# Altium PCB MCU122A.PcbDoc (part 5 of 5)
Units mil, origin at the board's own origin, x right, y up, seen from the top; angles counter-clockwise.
Board outline 4950 x 3450 mil, 4 copper layers (Top Layer, Signal Layer 1, Signal Layer 2, Bottom Layer), stack 60 mil thick; 257 components, 158 nets, 848 pads, 1971 vias.
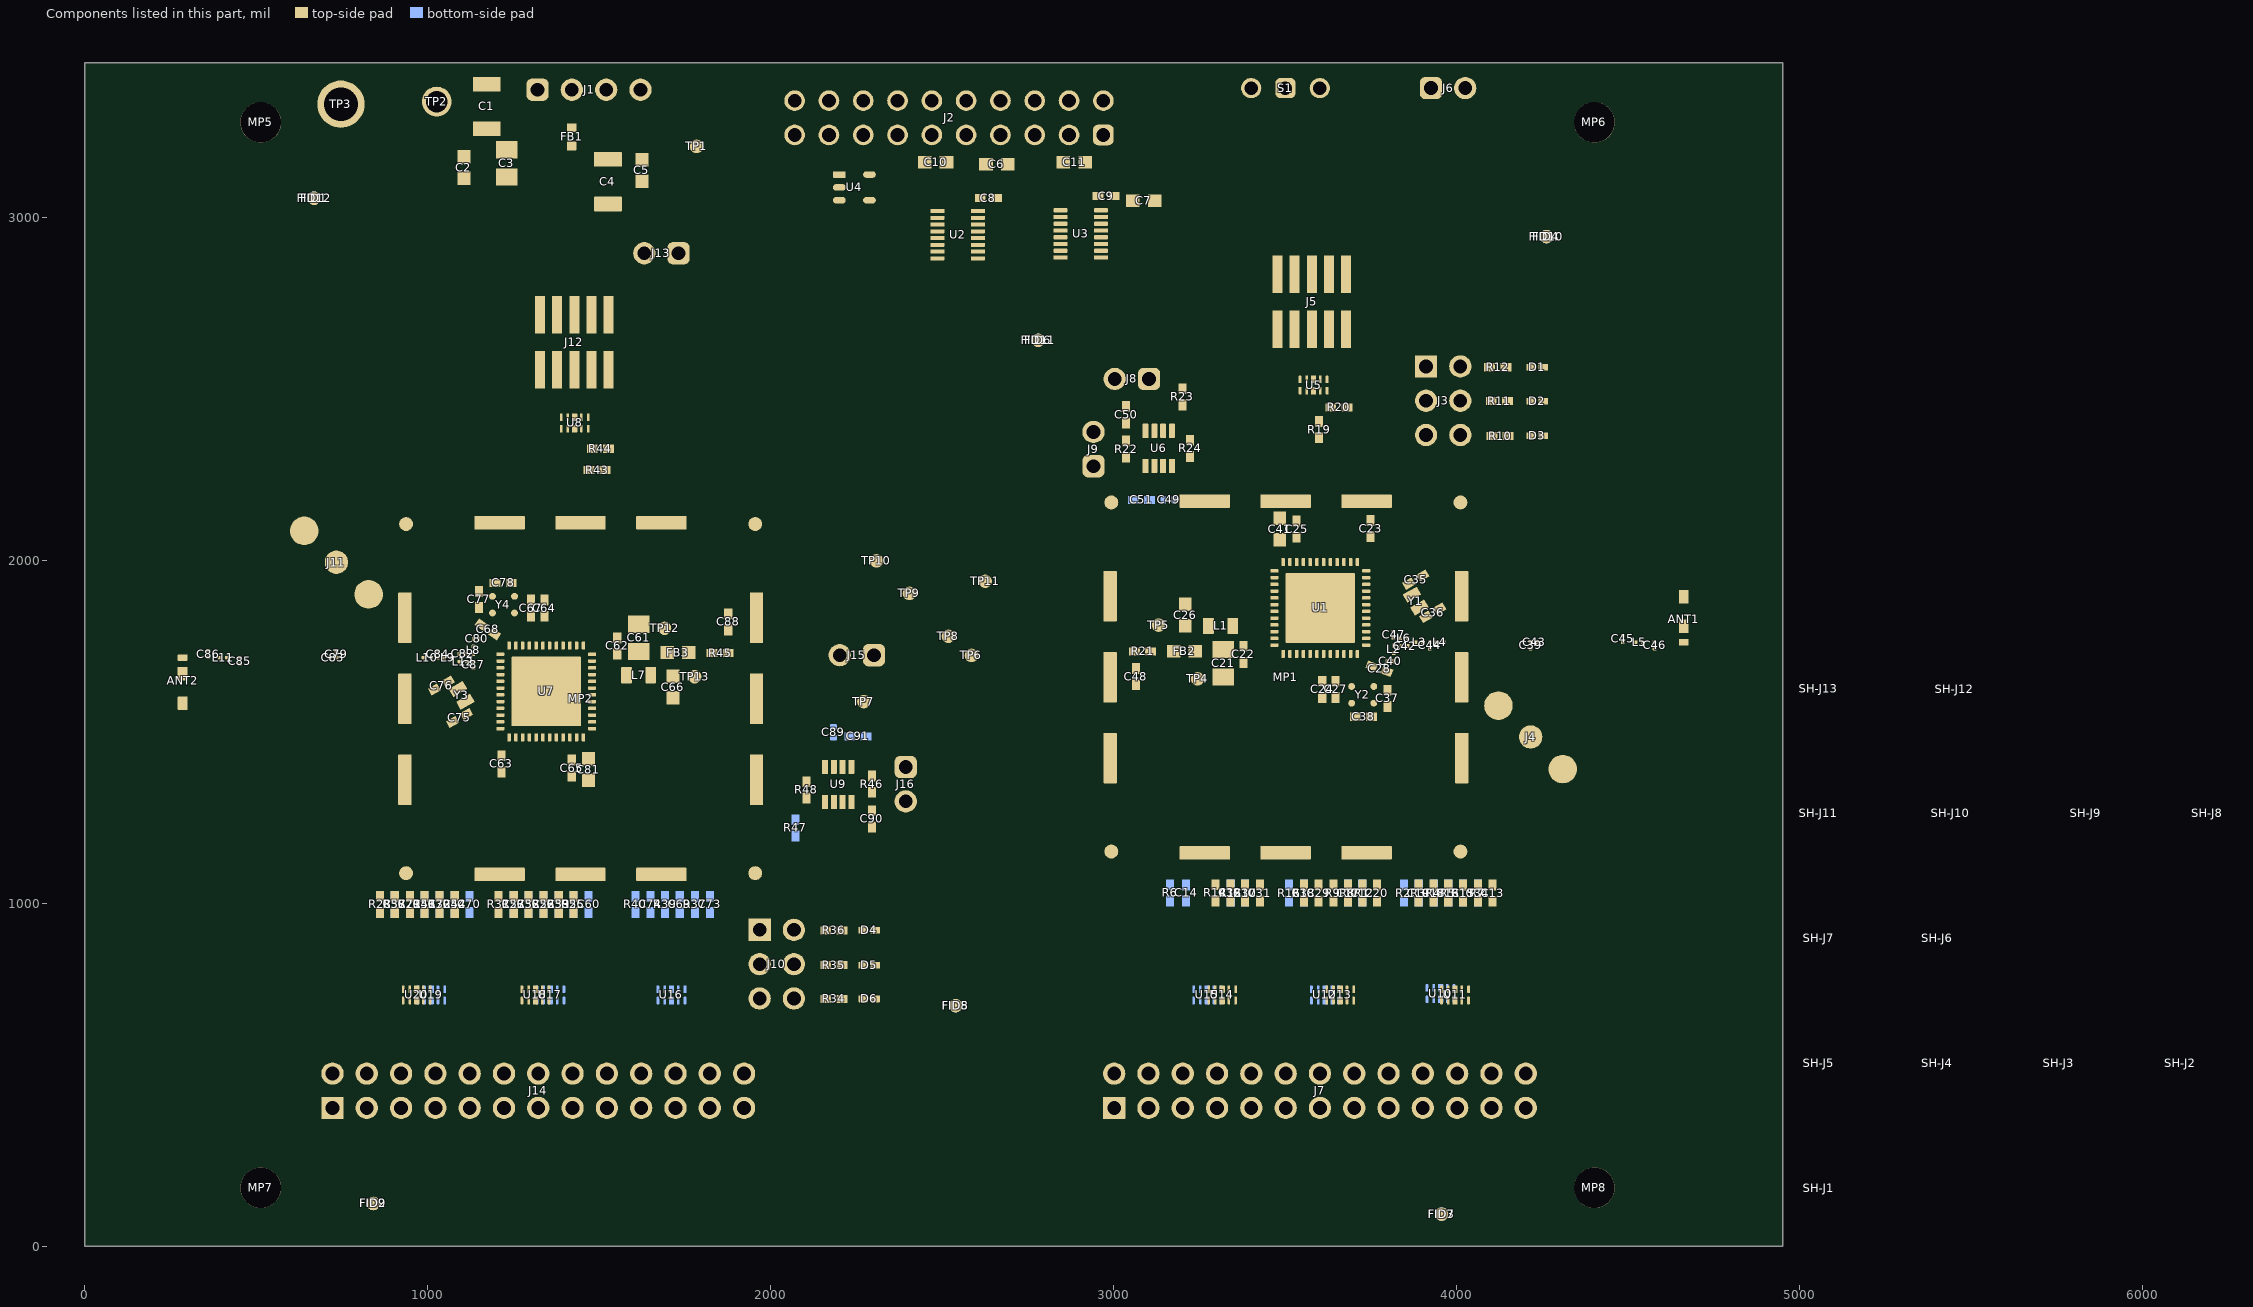
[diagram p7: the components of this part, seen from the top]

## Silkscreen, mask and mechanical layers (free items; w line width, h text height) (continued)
M9 Title Sheet:
  drawing of 57 lines, arcs and shapes, not listed
  text "1" at 739.84,8036.5 h70
  text "2" at 3235.5,8036.5 h70
  text "3" at 5724.84,8036.5 h70
  text "4" at 8231.51,8036.5 h70
  text "5" at 10730.5,8036.5 h70
  text "6" at 13235.5,8036.5 h70
  text "A" at -416.5,6893.5 h70
  text "A" at 14383.5,6893.5 h70
  text "B" at -416.5,4513.5 h70
  text "B" at 14383.5,4513.5 h70
  text "C" at -416.5,2138.5 h70
  text "C" at 14383.5,2138.5 h70
  text "PROJECT TITLE:" at 11343.5,277.5 h45
  text ".PRJ_Title" at 11393.5,144.17 h70
  text "DESIGNED FOR:" at 11343.5,-23.5 h45
  text ".PRJ_Customer" at 11393.5,-163.5 h70
  text "D" at -416.5,-231.5 h70
  text "D" at 14383.5,-231.5 h70
  text "FILE NAME:" at 11343.5,-323.5 h45
  text ".PCB_File_Name_No_Path" at 11393.5,-443.5 h70
  text "Texas Instruments (TI) and/or its licensors do not warrant the accuracy or completeness of this specification" at 6374,-605.34 h45
  text "ENGINEER:" at 11343.5,-613.5 h45
  text "LAYOUT BY:" at 12848.5,-613.5 h45
  text "or any information contained therein. TI and/or its licensors do not warrant that this design will meet" at 6329.01,-718 h45
  text ".PRJ_Engineer" at 11393.5,-768.49 h70
  text ".PCB_Layout" at 12899,-768.49 h70
  text "the specifications, will be suitable for your application or fit for any particular purpose, or will operate in" at 6329.01,-830.67 h45
  text ".Layer_Name" at 577,-858.49 h60
  text "ALTIUM DESIGNER VERSION:" at 12848.5,-923.5 h45
  text "an implementation. TI and/or its licensors do not warrant that the design is production worthy. You should" at 6329.01,-943.33 h45
  text "completely validate and test your design implementation to confirm the system functionality for your application." at 6374,-1056 h45
  text ".print_Scale" at 11393.5,-1056.83 h70
  text ".Application_BuildNumber" at 12899,-1056.83 h70
  text "1" at 739.84,-1263.5 h70
  text "2" at 3235.5,-1263.5 h70
  text "3" at 5724.84,-1263.5 h70
  text "4" at 8231.51,-1263.5 h70
  text "5" at 10730.5,-1263.5 h70
  text "6" at 13235.5,-1263.5 h70
M10 Fab Notes:
  drawing of 189 lines, arcs and shapes, not listed
  text "DESIGN INFORMATION" at 12382.02,6356.17 h60
  text "MIN. TRACK WIDTH:" at 11737.46,6224.05 h60
  text "6.5" at 12785.43,6224.05 h60
  text "MIL" at 12988.46,6224.05 h60
  text "Notes" at 7057.24,6141.89 h60
  text "5" at 12834.65,6112.2 h60
  text "MIN. CLEARANCE:" at 11737.46,6099.92 h60
  text "MIL" at 12988.46,6099.92 h60
  text "RF Nets must maintain 50ohm characteristic impedance +/-10%" at 7047.4,6033.93 h60
  text "MIN. VIA PAD SIZE:" at 11737.46,5975.8 h60
  text "11.457" at 12610.85,5975.8 h60
  text "MIL" at 12988.46,5975.8 h60
  text "RF nets are GCPW lines with 6.5mil width and ~6.25mil gap to GND" at 7047.4,5935.51 h60
  text "0.05mm (2MIL)" at 12432.46,5845.9 h60
  text "MINIMUM ANNULAR RING" at 11408.23,5837.67 h60
  text "EXTERNAL" at 13140.46,5837.67 h60
  text "PER" at 11608.23,5727.55 h60
  text "IPC-D-275 CLASS 2 LEVEL C" at 11828.23,5727.54 h60
  text "MIL, HOLES" at 13316.46,5627.07 h60
  text "+/-" at 12924,5618.48 h60
  text "+/-" at 13778,5618.48 h60
  text "REGISTRATION TOLERANCES:" at 11408.23,5617.42 h60
  text "METAL" at 12608,5617.42 h60
  text "5" at 13184.2,5617.42 h60
  text "3" at 14017.2,5617.42 h60
  text "MIL" at 14133.46,5617.42 h60
  text "HOLE SIZE TOLERANCE (UNLESS OTHERWISE SPECIFIED):" at 11408.23,5519.1 h60
  text "+/-" at 13778,5516.23 h60
  text "3" at 14017.2,5515.17 h60
  text "MIL" at 14133.46,5515.17 h60
  text "MATERIAL:" at 11333.46,5377.52 h60
  text "FR-4 High Tg" at 12319.9,5249 h60
  text "X" at 12175.46,5241.01 h60
  text "FR-4" at 11754.46,5236.49 h60
  text "OTHER" at 13242.46,5236.49 h60
  text "X" at 11958.66,5093.46 h60
  text "62 MIL (1.6mm) +/-10%" at 12074.56,5093.46 h60
  text "THICKNESS:" at 11408.23,5085.24 h60
  text "OTHER" at 13359.46,5085.24 h60
  text "TOLERANCE:" at 11408.23,4946.92 h60
  text "X" at 12256.46,4946.92 h60
  text "ANSI IPC-6012 TYPE 3 CLASS 2" at 12434.48,4946.92 h60
  text "OTHER +/-" at 12434.46,4802.73 h60
  text "BOW & TWIST:" at 11408.23,4657.54 h60
  text "X" at 12256.46,4657.54 h60
  text "ANSI IPC-6012 TYPE 3 CLASS 2" at 12434.48,4657.54 h60
  text "OTHER +/-" at 12434.46,4510.85 h60
  text "DRILLING:" at 11333.46,4380.23 h60
  text "NC_DRILL FILES" at 13094.46,4275.04 h60
  text "REFERENCE:" at 11408.23,4271.1 h60
  text "X" at 12065.46,4271.01 h60
  text "AS SHOWN" at 12243.46,4271.1 h60
  text "X" at 12966.46,4271.1 h60
  text "X" at 13287.4,4128.85 h60
  text "OTHER" at 13392.46,4128.85 h60
  text "PTH COPPER THICKNESS:" at 11407.91,4125.32 h60
  text "20-30 um" at 12675.14,4125.32 h60
  text "36 um" at 13769.84,4124.17 h60
  text "BOARD FINISH:" at 11333.46,3977.73 h60
  text "SILKSCREEN:" at 11488.68,3867.6 h60
  text "X" at 12446.46,3867.6 h60
  text "TOP" at 12563.46,3867.6 h60
  text "X" at 12956.46,3867.6 h60
  text "BOTTOM" at 13074.46,3867.6 h60
  text "SILKSCREEN COLOR:" at 11488.68,3712.41 h60
  text "X" at 12445.46,3712.41 h60
  text "WHITE" at 12563.46,3712.41 h60
  text "OTHER" at 13074.46,3712.41 h60
  text "X" at 13169.29,3582.68 h60
  text "GREEN" at 12694.46,3568.96 h60
  text "OTHER" at 13312.46,3568.96 h60
  text "SOLDER RESIST COLOR:" at 11488.68,3562.1 h60
  text "RED" at 13669,3550.03 h60
  text "X" at 12576.46,3414.71 h60
  text "MATTE" at 12694.46,3414.71 h60
  text "SEMI-GLOSS" at 13312,3414.07 h60
  text "IMMERSION GOLD (ENIG)" at 12394.46,3241.94 h60
  text "ENEPIG" at 13732,3234.72 h60
  text "SURFACE FINISH:" at 11333.46,3233.72 h60
  text "X" at 12216.46,3233.72 h60
  text "IMM. TIN/SILVER OR EQUIV" at 11663,3096.4 h60
  text "OTHER" at 13094.46,3092.47 h60
  text "ARRAY/PANEL:" at 11333.46,2937.09 h60
  text "CUT AND TRIM PER M1 BOARD OUTLINE" at 12394.46,2928.87 h60
  text "N.C. ROUTE" at 12394.46,2792.9 h60
  text "X" at 13082.46,2792.9 h60
  text "V. SCORE" at 13260.46,2792.9 h60
  text "CERTIFICATION:" at 11333.46,2663.77 h60
  text "MATERIALS AND WORKMANSHIP FOR ALL PCBS" at 12058.46,2663.77 h60
  text "TO MEET OR EXCEED THE REQUIREMENTS OF:" at 12058.46,2569.71 h60
  text "X" at 11695.97,2441.08 h60
  text "ANSI IPC-A-600F CLASS ->" at 11823.96,2441.08 h60
  text "X" at 13471.97,2441.08 h60
  text "2" at 13581.96,2441.08 h60
  text "1" at 13266.96,2439.58 h60
  text "3" at 13935.96,2439.58 h60
  text "X" at 12507.97,2293.39 h60
  text "RoHS" at 12635.96,2293.39 h60
  text "OTHER" at 13280.36,2293.39 h60
  text "PER ORDER" at 13677.42,2293.39 h60
  text "ALL BOARDS MUST MEET OR EXCEED UL94-V0 REQUIREMENTS." at 11361,2139.57 h60
  text "PCB MUST BEAR THE UL94V-0 UL REGISTERED MATERIAL ID NUMBER" at 11361,2023.5 h60
  text "ADDITIONAL REQUIREMENTS:" at 11333.46,1854.08 h60
  text "MICROSECTION:" at 11408.23,1746.95 h60
  text "YES" at 12313.96,1746.95 h60
  text "REQUIRED" at 13175.46,1602.62 h60
  text "BARE BOARD ELEC. TEST:" at 11408.23,1599.76 h60
  text "NONE" at 12713.96,1599.76 h60
  text "X" at 13057.46,1599.76 h60
  text "PER ORDER" at 13767.46,1599.76 h60
  text "XX MIL VIAS REQUIRE NON-CONDUCTIVE FILL AND PLANARIZE" at 11576.38,1394.82 h59
  text "XX MIL VIAS REQUIRE CONDUCTIVE FILL AND PLANARIZE" at 11584.38,1290.84 h60
  text "OUTER XX MIL TRACES REQUIRE 50 OHM SINGLE-ENDED IMPEDANCE" at 11583.39,1127.46 h58
  text "LAYER 2 & 3 (INNER LAYERS) XX MIL WIDE, XX MIL SPACE / TRACES REQUIRE 100 OHM DIFFERENTIAL IMPEDANCE" at 11575.39,891.74 h60
  text ".Layer_Name" at 577,-858.49 h60
M11 Gerber Information:
  lines w10: -292,-930.17 6308,-930.17 ; -292,-726.83 6310,-726.83 ; -292,-523.5 -292,-1133.5 3713,-1133.5 6310,-1133.5 6310,-523.5 -291.5,-523.5 -291.5,-1133.5 1284,-1133.5 ; 2173,-1133.5 2173,-523.5 ; 3440,-726.83 3440,-523.5 ; 4280,-726.83 4280,-523.5 ; 4902,-1140 4902,-937.17
  text "ALL ARTWORK VIEWED FROM TOP SIDE" at -228.5,-655.67 h60
  text "BOARD #:" at 2248,-655.67 h60
  text ".PRJ_Number" at 2793.5,-655.67 h60
  text "REV:" at 3638,-655.67 h60
  text ".PCB_Rev" at 3929.5,-655.67 h60
  text "SVN REV:" at 4476,-655.67 h60
  text ".VersionControl_RevNumber" at 4982,-655.67 h60
  text "LAYER NAME =" at -228.5,-858.49 h60
  text "TID #:" at 2248,-859 h60
  text ".TID" at 2793.5,-859 h60
  text "PLOT NAME =" at -228.5,-1064.34 h60
  text ".plot_File_Name" at 577,-1064.34 h60
  text "GENERATED    :" at 2250,-1064.34 h60
  text ".Print_Date" at 3119.5,-1064.34 h60
  text ".Print_Time" at 3848.5,-1064.34 h60
  text "TEXAS INSTRUMENTS" at 5113,-1064.34 h60
M12 Stackup:
  drawing of 295 lines, arcs and shapes, not listed
  text "Layer" at 6750.34,7816.15 h60
  text "Name" at 7160.25,7816.15 h60
  text "Material" at 8099.99,7816.15 h60
  text "Thickness" at 8959.76,7816.15 h60
  text "Constant" at 9609.6,7816.15 h60
  text "Board Layer Stack" at 10179.46,7816.15 h60
  text "Top Overlay" at 7160.25,7696.15 h60
  text "Top Solder" at 7160.25,7576.15 h60
  text "Solder Resist" at 8099.99,7576.15 h60
  text "1.00mil" at 8959.76,7576.15 h60
  text "3.4" at 9609.6,7576.15 h60
  text "1" at 6750.34,7456.15 h60
  text "Top Layer" at 7160.25,7456.15 h60
  text "1.60mil" at 8959.76,7456.15 h60
  text "Dielectric 1" at 7160.25,7336.15 h60
  text "FR-4 High Tg" at 8099.99,7336.15 h60
  text "5.00mil" at 8959.76,7336.15 h60
  text "4.6" at 9609.6,7336.15 h60
  text "2" at 6750.34,7216.15 h60
  text "Signal Layer 1" at 7160.25,7216.15 h60
  text "1.40mil" at 8959.76,7216.15 h60
  text "Dielectric 2" at 7160.25,7096.15 h60
  text "FR-4 High Tg" at 8099.99,7096.15 h60
  text "44.00mil" at 8959.76,7096.15 h60
  text "4.6" at 9609.6,7096.15 h60
  text "3" at 6750.34,6976.15 h60
  text "Signal Layer 2" at 7160.25,6976.15 h60
  text "1.40mil" at 8959.76,6976.15 h60
  text "Dielectric 3" at 7160.25,6856.15 h60
  text "FR-4 High Tg" at 8099.99,6856.15 h60
  text "5.00mil" at 8959.76,6856.15 h60
  text "4.6" at 9609.6,6856.15 h60
  text "4" at 6750.34,6736.15 h60
  text "Bottom Layer" at 7160.25,6736.15 h60
  text "1.60mil" at 8959.76,6736.15 h60
  text "Bottom Solder" at 7160.25,6616.15 h60
  text "Solder Resist" at 8099.99,6616.15 h60
  text "1.00mil" at 8959.76,6616.15 h60
  text "3.4" at 9609.6,6616.15 h60
  text "Bottom Overlay" at 7160.25,6496.15 h60
  text "Total board thickness:" at 6750.34,6376.15 h60
  text "62.00mil" at 8959.76,6376.15 h60
  text ".Layer_Name" at 577,-858.49 h60
M13 Component Bodies Top:
  text ".Layer_Name" at 577,-858.49 h60
M14 Component Bodies Bottom:
  text ".Layer_Name" at 577,-858.49 h60
M15 Courtyards Top:
  text ".Layer_Name" at 577,-858.49 h60
M16 Courtyards Bottom:
  text ".Layer_Name" at 577,-858.49 h60
Drill Drawing:
  circle w10: c5363.72,3165.96 r27.63
  circle w10: c5363.72,2917.32 r27.63
  lines w10: 5336.09,2447.67 5391.34,2447.67 5363.72,2392.42 5336.09,2447.67 ; 5336.09,2516.74 5391.34,2516.74 5391.34,2571.99 5336.09,2571.99 5336.09,2516.74 ; 5336.09,2654.87 5349.9,2654.87 5349.9,2641.06 5377.53,2641.06 5377.53,2654.87 5391.34,2654.87 5391.34,2682.5 5377.53,2682.5 5377.53,2696.31 5349.9,2696.31 5349.9,2682.5 5336.09,2682.5 5336.09,2654.87 ; 5336.09,2765.38 5363.72,2779.19 5391.34,2765.38 5377.53,2793 5391.34,2820.63 5363.72,2806.82 5336.09,2820.63 5349.9,2793 5336.09,2765.38 ; 5336.09,3069.27 5391.34,3069.27 5363.72,3014.02 5336.09,3069.27 ; 5336.09,3290.28 5363.72,3262.66 5391.34,3290.28 5363.72,3317.91 5336.09,3290.28 ; 5347.14,3058.22 5380.29,3058.22 5363.72,3025.07 5347.14,3058.22
  lines w12: 5286,2355.12 8517.65,2355.12 ; 5286,3349.68 8517.65,3349.68 ; 5623.86,2230.8 5623.86,3474 ; 5956.03,2230.8 5956.03,3474 ; 6592.59,2230.8 6592.59,3474 ; 6851.73,2230.8 6851.73,3474 ; 7226.89,2230.8 7226.89,3474 ; 7951.22,2230.8 7951.22,3474 ; 5286,2230.8 8517.65,2230.8 8517.65,3474 5286,3474 5286,2230.8
  text "Symbol" at 5360.59,3386.98 h72
  text "Quantity" at 5661.16,3386.98 h72
  text "Finished Hole Size" at 5993.33,3386.98 h72
  text "Plated" at 6629.89,3386.98 h72
  text "Hole Type" at 6889.03,3386.98 h72
  text "Drill Layer Pair" at 7264.19,3386.98 h72
  text "Hole Tolerance" at 7988.52,3386.98 h72
  text "4" at 5661.16,3262.66 h60
  text "118.11mil (3.000mm)" at 5993.33,3262.66 h60
  text "NPTH" at 6629.89,3262.66 h60
  text "Round" at 6889.03,3262.66 h60
  text "Top Layer - Bottom Layer" at 7264.19,3262.66 h60
  text "1970" at 5661.16,3138.34 h60
  text "8.00mil (0.203mm)" at 5993.33,3138.34 h60
  text "PTH" at 6629.89,3138.34 h60
  text "Round" at 6889.03,3138.34 h60
  text "Top Layer - Bottom Layer" at 7264.19,3138.34 h60
  text "1" at 5661.16,3014.02 h60
  text "8.00mil (0.203mm)" at 5993.33,3014.02 h60
  text "PTH" at 6629.89,3014.02 h60
  text "Round" at 6889.03,3014.02 h60
  text "Top Layer - Bottom Layer" at 7264.19,3014.02 h60
  text "3" at 5661.16,2889.7 h60
  text "39.37mil (1.000mm)" at 5993.33,2889.7 h60
  text "PTH" at 6629.89,2889.7 h60
  text "Round" at 6889.03,2889.7 h60
  text "Top Layer - Bottom Layer" at 7264.19,2889.7 h60
  text "+/-11.81mil" at 7988.52,2889.7 h60
  text "80" at 5661.16,2765.38 h60
  text "40.00mil (1.016mm)" at 5993.33,2765.38 h60
  text "PTH" at 6629.89,2765.38 h60
  text "Round" at 6889.03,2765.38 h60
  text "Top Layer - Bottom Layer" at 7264.19,2765.38 h60
  text "20" at 5661.16,2641.06 h60
  text "40.16mil (1.020mm)" at 5993.33,2641.06 h60
  text "PTH" at 6629.89,2641.06 h60
  text "Round" at 6889.03,2641.06 h60
  text "Top Layer - Bottom Layer" at 7264.19,2641.06 h60
  text "+/-7.87mil" at 7988.52,2641.06 h60
  text "1" at 5661.16,2516.74 h60
  text "63.00mil (1.600mm)" at 5993.33,2516.74 h60
  text "PTH" at 6629.89,2516.74 h60
  text "Round" at 6889.03,2516.74 h60
  text "Top Layer - Bottom Layer" at 7264.19,2516.74 h60
  text "1" at 5661.16,2392.42 h60
  text "98.43mil (2.500mm)" at 5993.33,2392.42 h60
  text "PTH" at 6629.89,2392.42 h60
  text "Round" at 6889.03,2392.42 h60
  text "Top Layer - Bottom Layer" at 7264.19,2392.42 h60
  text "2080 Total" at 5661.16,2268.1 h60
  text ".Layer_Name" at 577,-858.49 h60
M17 Embedded Cavity:
  text ".Layer_Name" at 577,-858.49 h60
M18 Embedded Assembly:
  text ".Layer_Name" at 577,-858.49 h60
M19 Embedded Keepout:
  text ".Layer_Name" at 577,-858.49 h60

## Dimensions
0,-400 to 1000,-400 on M2 Board Dimensions
0,0 to 0,3450 on M2 Board Dimensions
0,0 to 4950,0 on M2 Board Dimensions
